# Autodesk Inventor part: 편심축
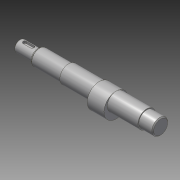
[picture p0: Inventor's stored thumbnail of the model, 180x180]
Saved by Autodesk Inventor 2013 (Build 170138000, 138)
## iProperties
Created: 2017-08
Part Number: 편심축
Material: 강철, 연강
Document SubType Name: Modeling
Designer: mduedu
Density: 1 g/cm^3
Author: mduedu
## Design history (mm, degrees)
sketch "스케치1"
  geometry: L1 (0, 0)-(142, 0); L2 (142, 0)-(142, 8.5); L3 (142, 8.5)-(127, 8.5); L4 (127, 8.5)-(127, 9.5); L5 (127, 9.5)-(49, 9.5); L6 (49, 9.5)-(49, 8.5); L7 (49, 8.5)-(20, 8.5); L8 (20, 8.5)-(20, 6); L9 (20, 6)-(0, 6); L10 (0, 6)-(0, 0)
  constraints: 20 end point, 6 parallel, 2 collinear, 2 perpendicular, 1 horizontal
  dimensions: "d0" = 142 distance of L1.start L1.end; "d1" = 17 diameter of L3 L1; "d2" = 19 diameter of L5 L1; "d3" = 12 diameter of L9 L1; "d4" = 20 distance of L8.end L9.end; "d5" = 15 distance of L2.end L3.end; "d6" = 78 distance of L4.end L5.end
revolve "회전1" sketch "스케치1" stored, may be unused: angle "d7" = 90 deg
node "작업 평면1"
sketch "스케치2"
  geometry: C1 r 9.5 at (0, 0) reference; C2 r 13 at (0, -3.5); 1 further point
  constraints: 1 centre point, 1 tangent, 1 vertical alignment
  dimensions: "d8" = 3.5 distance of point (0, 0) C2.centre
extrude "돌출1" join sketch "스케치2" stored distance "d9" = 18; taper "d10" = 0 deg
chamfer "모따기1" distance "d11" = 1; stored, may be unused: second distance "d12" = 2, angle "d13" = 45 deg
node "작업 평면2"
sketch "스케치3"
  geometry: L1 (4, -2)-(-4, -2); L2 (-4, -2)-(-4, 2); L3 (-4, 2)-(4, 2); L4 (4, 2)-(4, -2); L5 (10, 6)-(10, -6) reference; A1 r 2 centre (4, 0) between (4, -2) and (4, 2); A2 r 2 centre (-4, 0) between (-4, 2) and (-4, -2); A3 r 2 centre (4, 0) between (4, 2) and (4, -2); A4 r 2 centre (-4, 0) between (-4, -2) and (-4, 2); 1 further point
  constraints: 8 end point, 8 point on circle, 4 centre point, 2 midpoint, 2 parallel, 1 horizontal, 1 horizontal alignment, 1 perpendicular
  dimensions: "d14" = 12 dimension on A2 A1; "d16" = 4 distance between parallel lines of L3 L1; "d17" = 4 distance edge to line of A1 L5
extrude "돌출2" cut sketch "스케치3" distance "d18" = 2.5; taper "d19" = 0 deg
chamfer "모따기2" distance "d20" = 1; stored, may be unused: second distance "d21" = 2, angle "d22" = 45 deg
chamfer "모따기3" distance "d23" = 1; stored, may be unused: second distance "d24" = 2, angle "d25" = 60 deg
fillet "모깎기1" dims "d26" = 0.5, "d39" = 4
hole "구멍1" diameter "d29" = 3.242; stored, may be unused: countersink angle "d33" = 90 deg, drill point angle "d35" = 118 deg; dims "d30" = 8, "d31" = 4, "d32" = 2, "d34" = 10, "d36" = 10, "d37" = 10
node "솔리드1"
node "절단 모서리 투영1"
other parameters: "d38" = -39
